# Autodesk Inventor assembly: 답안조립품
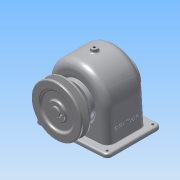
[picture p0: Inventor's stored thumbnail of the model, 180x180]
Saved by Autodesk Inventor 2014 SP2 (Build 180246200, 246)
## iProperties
Created: 2016-01
Part Number: 답안조립품
Document SubType Name: Assembly
Designer: User
Author: User
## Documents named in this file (16)
- C:\Documents and Settings\User\My Documents\Inventor\460106V1013\답안조립품.iam
- C:\Documents and Settings\User\My Documents\Inventor\460106V1013\본체.ipt
- C:\Documents and Settings\User\My Documents\Inventor\460106V1013\축.ipt
- C:\Documents and Settings\User\My Documents\Inventor\460106V1013\뒤커버.ipt
- C:\Documents and Settings\User\My Documents\Inventor\460106V1013\베어링 6203.ipt
- C:\Documents and Settings\User\My Documents\Inventor\460106V1013\오일씰 28 40 8.ipt
- C:\Documents and Settings\User\My Documents\Inventor\460106V1013\부시1.ipt
- C:\Documents and Settings\User\My Documents\Inventor\460106V1013\부시2.ipt
- C:\Documents and Settings\User\My Documents\Inventor\460106V1013\스퍼기어.ipt
- C:\Documents and Settings\User\My Documents\Inventor\460106V1013\키 - 6 x 6 x 22.ipt
- C:\Documents and Settings\User\My Documents\Inventor\460106V1013\키 - 5 x 5 x 18.ipt
- C:\Documents and Settings\User\My Documents\Inventor\460106V1013\앞커버.ipt
- C:\Documents and Settings\User\My Documents\Inventor\460106V1013\V-벨트풀리.ipt
- C:\Documents and Settings\User\My Documents\Inventor\460106V1013\멈춤나사 - M4x10.ipt
- C:\Documents and Settings\User\My Documents\Inventor\460106V1013\볼트 M3 x 10.ipt
- C:\Documents and Settings\User\My Documents\Inventor\460106V1013\볼트 M3 x 8.ipt
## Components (9 placed, 3 different names)
1. V-벨트풀리:1
2. ISO 4762 M3 x 8:1
3. ISO 4762 M3 x 10:1
4. ISO 4762 M3 x 8:2
5. ISO 4762 M3 x 10:2
6. ISO 4762 M3 x 8:3
7. ISO 4762 M3 x 10:3
8. ISO 4762 M3 x 8:4
9. ISO 4762 M3 x 10:4
